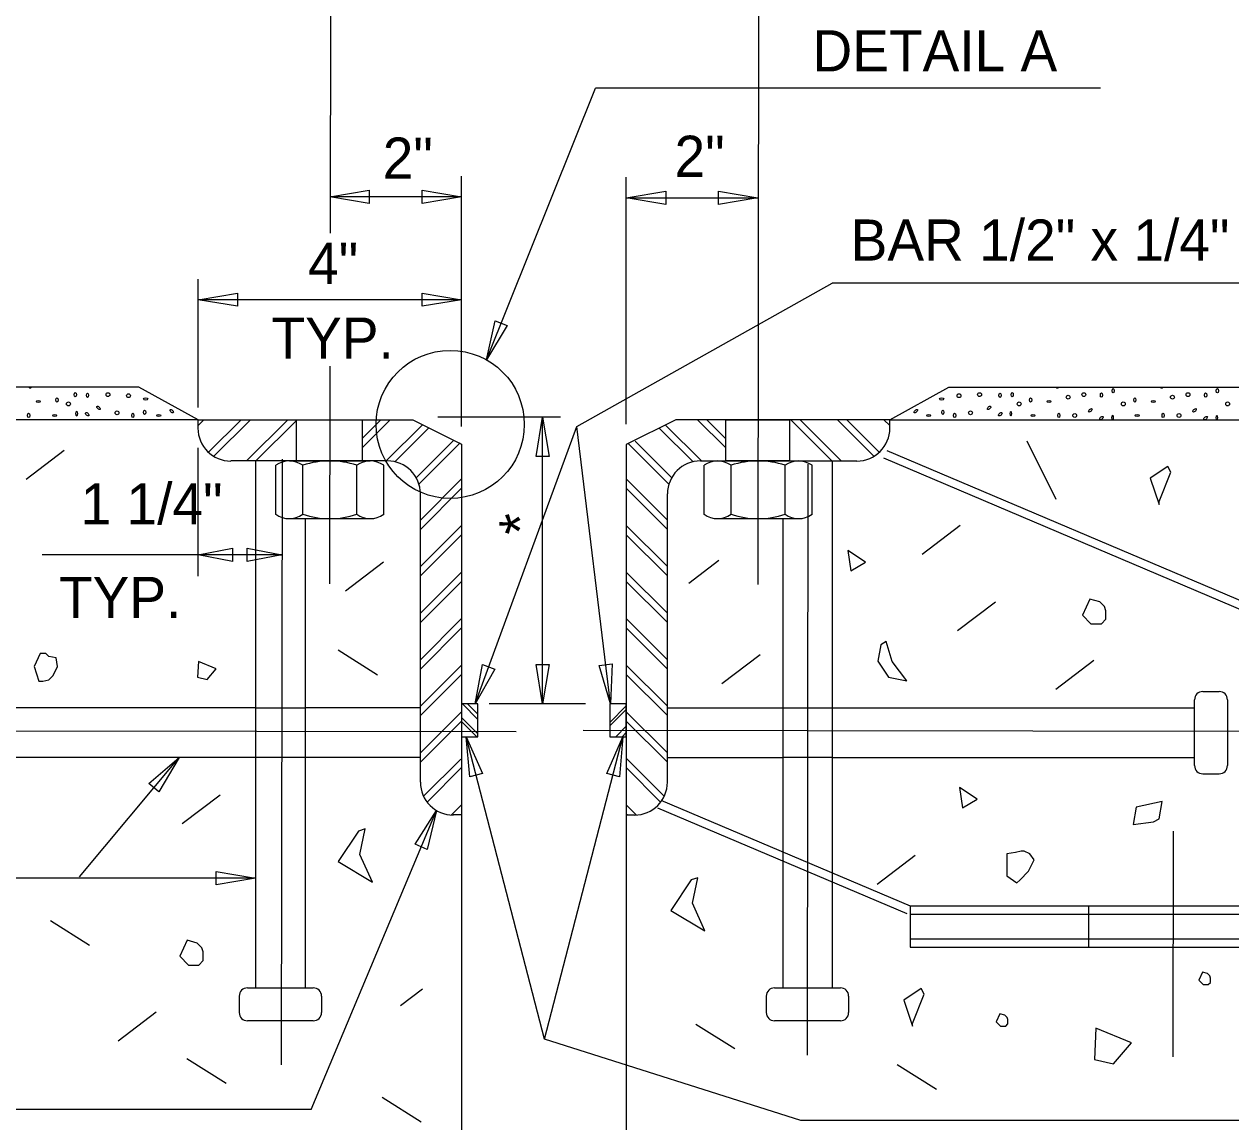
# Model space of a CAD drawing. Extents: x 0 to 11.3, y 0 to 7.8.
# Drawn here: x 2.195 to 3.721, y 1.702 to 3.091 of the extents above; entities that cross this region are included whole.
import ezdxf

# ---------------------------------------------------------------- set-up
doc = ezdxf.new("R2010")
doc.units = 0
for name, color, linetype in [('BRDG_ANNO_General-Notes', 7, 'Continuous'), ('BRDG_BASE_Dtlctrln', 7, 'Continuous'), ('BRDG_BASE_Hidden-Line', 7, 'Continuous'), ('BRDG_BASE_Obj-Line', 7, 'Continuous'), ('BRDG_BASE_Pattern', 7, 'Continuous')]:
    doc.layers.add(name, color=color, linetype=linetype)

msp = doc.modelspace()

# ---------------------------------------------------------------- linework, layer by layer
at = {"layer": 'BRDG_ANNO_General-Notes'}
for p, q in [((2.78, 2.6662), (2.9177, 3.0101)), ((3.5566, 3.0101), (2.9177, 3.0101)), ((2.7484, 2.5817), (2.7484, 2.8984)), ((2.9567, 2.5849), (2.9567, 2.8972)), ((2.5817, 2.8724), (2.6317, 2.8807)), ((2.7484, 2.8724), (2.5817, 2.8724)), ((2.6317, 2.8641), (2.5817, 2.8724)), ((2.6317, 2.8807), (2.6317, 2.8641)), ((2.6984, 2.8641), (2.6984, 2.8807)), ((2.6984, 2.8807), (2.7484, 2.8724)), ((2.7484, 2.8724), (2.6984, 2.8641)), ((2.9567, 2.8711), (3.0067, 2.8795)), ((2.9567, 2.8711), (3.1233, 2.8711)), ((3.0067, 2.8628), (2.9567, 2.8711)), ((3.0067, 2.8795), (3.0067, 2.8628)), ((3.0733, 2.8628), (3.0733, 2.8795)), ((3.0733, 2.8795), (3.1233, 2.8711)), ((3.1233, 2.8711), (3.0733, 2.8628)), ((2.4151, 2.6059), (2.4151, 2.7682)), ((2.8942, 2.5818), (3.2173, 2.7631)), ((3.7564, 2.7631), (3.2173, 2.7631)), ((2.4151, 2.7422), (2.4651, 2.7505)), ((2.4651, 2.7505), (2.4651, 2.7339)), ((2.6984, 2.7339), (2.6984, 2.7505)), ((2.6984, 2.7505), (2.7484, 2.7422)), ((2.7484, 2.7422), (2.4151, 2.7422)), ((2.4651, 2.7339), (2.4151, 2.7422)), ((2.7484, 2.7422), (2.6984, 2.7339)), ((2.78, 2.6662), (2.7908, 2.7157)), ((2.8063, 2.7095), (2.78, 2.6662)), ((2.7908, 2.7157), (2.8063, 2.7095)), ((2.8736, 2.5938), (2.7186, 2.5938)), ((2.7656, 2.2309), (2.8942, 2.5818)), ((2.8426, 2.5437), (2.8509, 2.5938)), ((2.8509, 2.2309), (2.8509, 2.5938)), ((2.8509, 2.5938), (2.8593, 2.5437)), ((2.9366, 2.2309), (2.8942, 2.5818)), ((2.4151, 2.3926), (2.4151, 2.5549)), ((2.8593, 2.5437), (2.8426, 2.5437)), ((2.4151, 2.4195), (2.4588, 2.4279)), ((2.4588, 2.4279), (2.4588, 2.4112)), ((2.4774, 2.4112), (2.4774, 2.4279)), ((2.4774, 2.4279), (2.5212, 2.4195)), ((2.4151, 2.4195), (2.2178, 2.4195)), ((2.5212, 2.4195), (2.4151, 2.4195)), ((2.4588, 2.4112), (2.4151, 2.4195)), ((2.5212, 2.4195), (2.4774, 2.4112)), ((2.5192, 2.4195), (2.5214, 2.4195)), ((2.7656, 2.2309), (2.7749, 2.2807)), ((2.7906, 2.2749), (2.7656, 2.2309)), ((2.7749, 2.2807), (2.7906, 2.2749)), ((2.8426, 2.2809), (2.8593, 2.2809)), ((2.8509, 2.2309), (2.8426, 2.2809)), ((2.8593, 2.2809), (2.8509, 2.2309)), ((2.9223, 2.2795), (2.9389, 2.2815)), ((2.9366, 2.2309), (2.9223, 2.2795)), ((2.9389, 2.2815), (2.9366, 2.2309)), ((2.905, 2.2309), (2.7833, 2.2309)), ((2.8534, 1.8065), (2.7544, 2.1892)), ((2.7589, 2.1387), (2.7544, 2.1892)), ((2.7544, 2.1892), (2.7749, 2.1429)), ((2.8534, 1.8065), (2.9526, 2.1892)), ((2.932, 2.1429), (2.9526, 2.1892)), ((2.9526, 2.1892), (2.9481, 2.1387)), ((2.2654, 2.0119), (2.3911, 2.1632)), ((2.3528, 2.1301), (2.3911, 2.1632)), ((2.3911, 2.1632), (2.3656, 2.1194)), ((2.7749, 2.1429), (2.7589, 2.1387)), ((2.9481, 2.1387), (2.932, 2.1429)), ((2.3656, 2.1194), (2.3528, 2.1301)), ((2.558, 1.7178), (2.7167, 2.0961)), ((2.6896, 2.0533), (2.7167, 2.0961)), ((2.7167, 2.0961), (2.705, 2.0468)), ((2.705, 2.0468), (2.6896, 2.0533)), ((2.438, 2.0021), (2.438, 2.0188)), ((2.438, 2.0188), (2.488, 2.0105)), ((2.488, 2.0105), (0.6091, 2.0105)), ((2.488, 2.0105), (2.438, 2.0021)), ((3.1774, 1.7036), (2.8534, 1.8065)), ((2.558, 1.7178), (0.6091, 1.7178)), ((3.7941, 1.7036), (3.1774, 1.7036))]:
    msp.add_line(p, q, dxfattribs=at)
msp.add_circle((2.7341, 2.5845), 0.0937, dxfattribs=at)
at = {"layer": 'BRDG_BASE_Dtlctrln'}
for p, q in [((2.5838, 4.2478), (2.5821, 2.8266)), ((3.1255, 4.2471), (3.1232, 2.3819)), ((2.5819, 2.6581), (2.5816, 2.3826)), ((2.5214, 2.5404), (2.5204, 1.7741)), ((3.1864, 2.5342), (3.1855, 1.7863)), ((1.9392, 2.1972), (2.8176, 2.1961)), ((2.9021, 2.1974), (3.7739, 2.1963)), ((3.6484, 2.0698), (3.6481, 1.7843))]:
    msp.add_line(p, q, dxfattribs=at)
at = {"layer": 'BRDG_BASE_Hidden-Line'}
for p, q in [((3.2861, 2.5516), (4.6168, 1.9868)), ((3.2821, 2.542), (4.6009, 1.9822)), ((2.488, 2.2257), (2.5505, 2.2257)), ((3.1546, 2.2257), (3.2171, 2.2257)), ((2.5505, 2.1632), (2.488, 2.1632)), ((3.2171, 2.1632), (3.1546, 2.1632)), ((3.0005, 2.109), (3.3156, 1.9752)), ((2.9964, 2.0994), (3.3115, 1.9656)), ((3.3156, 1.9752), (4.6168, 1.9752)), ((3.3156, 1.9752), (3.3156, 1.9231)), ((3.5415, 1.9752), (3.5415, 1.9231)), ((3.3161, 1.9648), (4.6174, 1.9648)), ((3.3156, 1.9231), (4.6168, 1.9231)), ((3.3161, 1.9335), (4.6168, 1.9335))]:
    msp.add_line(p, q, dxfattribs=at)
at = {"layer": 'BRDG_BASE_Obj-Line'}
for p, q in [((2.3403, 2.6315), (1.7493, 2.6315)), ((2.4151, 2.5903), (2.3403, 2.6315)), ((3.2901, 2.5903), (3.3648, 2.6315)), ((3.3648, 2.6315), (3.958, 2.6315)), ((2.4151, 2.5903), (1.7493, 2.5903)), ((2.4151, 2.5903), (2.6867, 2.5903)), ((2.4151, 2.5798), (2.4151, 2.5903)), ((2.6867, 2.5903), (2.7484, 2.5594)), ((3.0194, 2.5903), (2.9567, 2.5589)), ((3.2901, 2.5903), (3.0194, 2.5903)), ((3.2901, 2.5903), (3.958, 2.5903)), ((3.2901, 2.5798), (3.2901, 2.5903)), ((2.7484, 2.5594), (2.7484, 2.0903)), ((2.9567, 2.5589), (2.9567, 2.0903)), ((2.6546, 2.5382), (2.4567, 2.5382)), ((2.488, 2.5382), (2.488, 1.8715)), ((2.5192, 2.5382), (2.5192, 2.5382)), ((2.5309, 2.5382), (2.5818, 2.5382)), ((2.5818, 2.5382), (2.6327, 2.5382)), ((3.0505, 2.5382), (3.2484, 2.5382)), ((3.0726, 2.5382), (3.1234, 2.5382)), ((3.1234, 2.5382), (3.1743, 2.5382)), ((3.2171, 2.5382), (3.2171, 1.8715)), ((2.5134, 2.4707), (2.5134, 2.5328)), ((2.5476, 2.4707), (2.5476, 2.5328)), ((2.6159, 2.4707), (2.6159, 2.5328)), ((2.6502, 2.4707), (2.6502, 2.5328)), ((3.0551, 2.4707), (3.0551, 2.5328)), ((3.0893, 2.4707), (3.0893, 2.5328)), ((3.1576, 2.4707), (3.1576, 2.5328)), ((3.1918, 2.4707), (3.1918, 2.5328)), ((2.6963, 2.1319), (2.6963, 2.4965)), ((3.0088, 2.1319), (3.0088, 2.4965)), ((2.5309, 2.4653), (2.5818, 2.4653)), ((2.5505, 2.4653), (2.5505, 1.8715)), ((2.5818, 2.4653), (2.6327, 2.4653)), ((3.0726, 2.4653), (3.1234, 2.4653)), ((3.1234, 2.4653), (3.1743, 2.4653)), ((3.1546, 2.4653), (3.1546, 1.8715)), ((3.6859, 2.2465), (3.7067, 2.2465)), ((3.6755, 2.2257), (3.6755, 2.2361)), ((3.7171, 2.2361), (3.7171, 2.1528)), ((2.488, 2.2257), (2.0296, 2.2257)), ((2.6963, 2.2257), (2.5505, 2.2257)), ((3.0088, 2.2257), (3.1546, 2.2257)), ((3.2171, 2.2257), (3.6755, 2.2257)), ((3.6755, 2.1528), (3.6755, 2.2257)), ((2.6963, 2.1944), (2.6963, 2.1944)), ((3.0088, 2.1944), (3.0088, 2.1944)), ((2.488, 2.1632), (2.0296, 2.1632)), ((2.6963, 2.1632), (2.5505, 2.1632)), ((3.0088, 2.1632), (3.1546, 2.1632)), ((3.2171, 2.1632), (3.6755, 2.1632)), ((3.6859, 2.1423), (3.7067, 2.1423)), ((2.7484, 2.0903), (2.738, 2.0903)), ((2.7484, 2.0903), (2.7484, 1.3157)), ((2.9567, 2.0903), (2.9567, 1.3157)), ((2.9567, 2.0903), (2.9671, 2.0903)), ((3.3156, 1.9752), (3.3156, 1.9752)), ((2.4776, 1.8715), (2.5505, 1.8715)), ((2.5505, 1.8715), (2.5609, 1.8715)), ((3.1442, 1.8715), (3.2171, 1.8715)), ((3.2171, 1.8715), (3.2276, 1.8715)), ((2.4671, 1.8611), (2.4671, 1.8403)), ((2.5713, 1.8611), (2.5713, 1.8403)), ((3.1338, 1.8611), (3.1338, 1.8403)), ((3.238, 1.8611), (3.238, 1.8403)), ((2.5609, 1.8298), (2.4776, 1.8298)), ((3.2276, 1.8298), (3.1442, 1.8298))]:
    msp.add_line(p, q, dxfattribs=at)
for points in [[(2.5395, 2.5903), (2.6228, 2.5903), (2.6228, 2.5382), (2.5395, 2.5382)], [(3.0827, 2.5903), (3.1633, 2.5903), (3.1633, 2.5382), (3.0827, 2.5382)], [(2.7484, 2.2309), (2.7484, 2.1892), (2.7692, 2.1892), (2.7692, 2.2309)], [(2.9359, 2.2309), (2.9359, 2.1892), (2.9567, 2.1892), (2.9567, 2.2309)]]:
    msp.add_lwpolyline(points, close=True, dxfattribs=at)
msp.add_lwpolyline([(2.9577, 2.0903), (2.9567, 2.0913)], dxfattribs=at)
for centre, radius, start, end in [((2.4567, 2.5798), 0.0417, 180, 270), ((3.2484, 2.5798), 0.0417, 270, 0), ((2.5305, 2.5086), 0.0296, 54.7697, 125.2303), ((2.5818, 2.4278), 0.1104, 71.9685, 108.0316), ((2.633, 2.5086), 0.0296, 54.7697, 125.2303), ((2.6546, 2.4965), 0.0417, 0, 90), ((3.0505, 2.4965), 0.0417, 90, 180), ((3.0722, 2.5086), 0.0296, 54.7697, 125.2303), ((3.1234, 2.4278), 0.1104, 71.9685, 108.0316), ((3.1747, 2.5086), 0.0296, 54.7697, 125.2303), ((2.5305, 2.4949), 0.0296, 234.7697, 305.2303), ((2.5818, 2.5757), 0.1104, 251.9684, 288.0315), ((2.633, 2.4949), 0.0296, 234.7697, 305.2303), ((3.0722, 2.4949), 0.0296, 234.7697, 305.2303), ((3.1234, 2.5757), 0.1104, 251.9684, 288.0315), ((3.1747, 2.4949), 0.0296, 234.7697, 305.2303), ((3.6859, 2.2361), 0.0104, 90, 180), ((3.7067, 2.2361), 0.0104, 0, 90), ((3.6859, 2.1528), 0.0104, 180, 270), ((3.7067, 2.1528), 0.0104, 270, 0), ((2.738, 2.1319), 0.0417, 180, 270), ((2.9671, 2.1319), 0.0417, 270, 0), ((2.4776, 1.8611), 0.0104, 90, 180), ((2.5609, 1.8611), 0.0104, 0, 90), ((3.1442, 1.8611), 0.0104, 90, 180), ((3.2276, 1.8611), 0.0104, 0, 90), ((2.4776, 1.8403), 0.0104, 180, 270), ((2.5609, 1.8403), 0.0104, 270, 0), ((3.1442, 1.8403), 0.0104, 180, 270), ((3.2276, 1.8403), 0.0104, 270, 0)]:
    msp.add_arc(centre, radius, start, end, dxfattribs=at)
at = {"layer": 'BRDG_BASE_Pattern'}
for p, q in [((2.6532, 2.5382), (2.6985, 2.5835)), ((2.6639, 2.5371), (2.7069, 2.5801)), ((3.0412, 2.5371), (2.9984, 2.5799)), ((3.0519, 2.5382), (3.0064, 2.5837)), ((2.2457, 2.5514), (2.1976, 2.5148)), ((2.6909, 2.517), (2.7378, 2.5639)), ((3.0142, 2.517), (2.9678, 2.5634)), ((3.4633, 2.5636), (3.4999, 2.4901)), ((3.3791, 2.4564), (3.3309, 2.4197)), ((3.0738, 2.4121), (3.0359, 2.3833)), ((2.6498, 2.4103), (2.6017, 2.3736)), ((3.4238, 2.3597), (3.3757, 2.3231)), ((2.5924, 2.2991), (2.6419, 2.2678)), ((3.1259, 2.293), (3.0778, 2.2564)), ((3.5481, 2.2857), (3.4999, 2.2491)), ((2.4431, 2.1155), (2.3949, 2.0789)), ((3.322, 2.039), (3.2739, 2.0024)), ((2.2284, 1.9568), (2.278, 1.9256)), ((2.6991, 1.87), (2.6713, 1.8489)), ((2.362, 1.8407), (2.3139, 1.8041)), ((3.0448, 1.8258), (3.0942, 1.7947)), ((2.401, 1.782), (2.4505, 1.7508)), ((3.2995, 1.7747), (3.349, 1.7434)), ((2.6479, 1.7333), (2.6973, 1.7022))]:
    msp.add_line(p, q, dxfattribs=at)
for points in [[(2.4151, 2.5829), (2.4224, 2.5903)], [(2.4285, 2.5492), (2.4695, 2.5903)], [(2.4352, 2.5441), (2.4813, 2.5903)], [(2.4764, 2.5382), (2.5285, 2.5903)], [(2.4882, 2.5382), (2.5395, 2.5895)], [(2.6231, 2.5553), (2.6581, 2.5903)], [(2.6232, 2.5671), (2.6463, 2.5903)], [(3.0822, 2.5551), (3.047, 2.5903)], [(3.0827, 2.5664), (3.0588, 2.5903)], [(3.2169, 2.5382), (3.1648, 2.5903)], [(3.2287, 2.5382), (3.1766, 2.5903)], [(3.2699, 2.5441), (3.2238, 2.5903)], [(3.2766, 2.5492), (3.2356, 2.5903)], [(3.2901, 2.5829), (3.2827, 2.5903)], [(2.6944, 2.5088), (2.7468, 2.5611)], [(3.0107, 2.5088), (2.9596, 2.5598)], [(2.6963, 2.4634), (2.7484, 2.5156)], [(2.6963, 2.4517), (2.7484, 2.5038)], [(3.0088, 2.4634), (2.9567, 2.5156)], [(3.0088, 2.4517), (2.9567, 2.5038)], [(2.6963, 2.4045), (2.7484, 2.4566)], [(2.6963, 2.3928), (2.7484, 2.4448)], [(3.0088, 2.4045), (2.9567, 2.4566)], [(3.0088, 2.3928), (2.9567, 2.4448)], [(2.6963, 2.3456), (2.7484, 2.3977)], [(3.0088, 2.3456), (2.9567, 2.3977)], [(2.6963, 2.3338), (2.7484, 2.3859)], [(3.0088, 2.3338), (2.9567, 2.3859)], [(2.6963, 2.2867), (2.7484, 2.3388)], [(3.0088, 2.2867), (2.9567, 2.3388)], [(2.6963, 2.2749), (2.7484, 2.327)], [(3.0088, 2.2749), (2.9567, 2.327)], [(2.6963, 2.2278), (2.7484, 2.2798)], [(3.0088, 2.2278), (2.9567, 2.2798)], [(2.6963, 2.216), (2.7484, 2.2681)], [(3.0088, 2.216), (2.9567, 2.2681)], [(2.7692, 2.2112), (2.7496, 2.2309)], [(2.7692, 2.2178), (2.7561, 2.2309)], [(2.6963, 2.1688), (2.7484, 2.2209)], [(2.7692, 2.1929), (2.7484, 2.2138)], [(2.9359, 2.2073), (2.9567, 2.2282)], [(2.9359, 2.2029), (2.9567, 2.2237)], [(3.0088, 2.1688), (2.9567, 2.2209)], [(2.6963, 2.157), (2.7484, 2.2092)], [(2.7678, 2.1892), (2.7484, 2.2087)], [(2.9434, 2.1892), (2.9567, 2.2026)], [(3.0088, 2.157), (2.9567, 2.2092)], [(2.9515, 2.1892), (2.9567, 2.1945)], [(2.7004, 2.114), (2.7473, 2.161)], [(3.0047, 2.114), (2.9567, 2.162)], [(2.7049, 2.1067), (2.7484, 2.1502)], [(3.0002, 2.1067), (2.9567, 2.1502)], [(2.7357, 2.0904), (2.7484, 2.1031)], [(2.9694, 2.0904), (2.9567, 2.1031)]]:
    msp.add_lwpolyline(points, dxfattribs=at)
for points in [[(3.6192, 2.5165), (3.6306, 2.4833), (3.6306, 2.4869), (3.6453, 2.5239), (3.6416, 2.5312)], [(3.237, 2.4249), (3.2407, 2.3991), (3.2592, 2.4102)], [(3.543, 2.3634), (3.5337, 2.3432), (3.5445, 2.332), (3.5578, 2.332), (3.5632, 2.3379), (3.5632, 2.3486), (3.5614, 2.354), (3.5556, 2.3599)], [(3.2789, 2.3057), (3.2748, 2.285), (3.2886, 2.2647), (3.3116, 2.2602), (3.2932, 2.2845), (3.2854, 2.3098)], [(2.2079, 2.278), (2.2137, 2.2596), (2.219, 2.2596), (2.2265, 2.2614), (2.2319, 2.2668), (2.2373, 2.278), (2.2358, 2.289), (2.2265, 2.2909), (2.2226, 2.2947), (2.2153, 2.2947)], [(2.4155, 2.2844), (2.4146, 2.2646), (2.4265, 2.2618), (2.438, 2.2752)], [(3.3784, 2.1252), (3.3821, 2.0993), (3.4006, 2.1104)], [(3.6015, 2.1001), (3.5978, 2.0781), (3.6236, 2.0818), (3.6309, 2.0854), (3.6346, 2.1075)], [(2.6181, 2.0699), (2.5924, 2.0314), (2.6357, 2.0054), (2.6199, 2.0405), (2.6266, 2.0726)], [(3.438, 2.0411), (3.438, 2.0132), (3.4506, 2.0043), (3.4545, 2.0079), (3.4653, 2.019), (3.4727, 2.0337), (3.4673, 2.0411), (3.4599, 2.0447), (3.4564, 2.0447), (3.4491, 2.0427)], [(3.0387, 2.0081), (3.013, 1.9696), (3.0562, 1.9436), (3.0405, 1.9787), (3.0471, 2.0108)], [(2.4015, 1.9318), (2.3922, 1.9116), (2.403, 1.9004), (2.4162, 1.9004), (2.4217, 1.9062), (2.4217, 1.917), (2.4198, 1.9223), (2.4141, 1.9283)], [(3.6855, 1.8914), (3.6809, 1.8812), (3.6863, 1.8756), (3.6929, 1.8756), (3.6956, 1.8785), (3.6956, 1.884), (3.6947, 1.8866), (3.6919, 1.8896)], [(3.3076, 1.8561), (3.3189, 1.8229), (3.3189, 1.8264), (3.3337, 1.8634), (3.3299, 1.8708)], [(3.4293, 1.8388), (3.4246, 1.8286), (3.4301, 1.823), (3.4367, 1.823), (3.4394, 1.826), (3.4394, 1.8314), (3.4385, 1.8341), (3.4356, 1.837)], [(3.5508, 1.8204), (3.549, 1.7808), (3.5729, 1.7753), (3.5959, 1.802)]]:
    msp.add_lwpolyline(points, close=True, dxfattribs=at)
for centre in [(2.2512, 2.6104), (2.3012, 2.6222), (2.3272, 2.6208), (3.3776, 2.6208), (3.4036, 2.6222), (3.4536, 2.6104), (3.5157, 2.619), (3.5354, 2.6222), (3.5854, 2.6104), (3.6475, 2.619), (3.6672, 2.6222), (3.7173, 2.6104), (2.3127, 2.5992), (3.3921, 2.5992), (3.5239, 2.5958), (3.6558, 2.5958)]:
    msp.add_circle(centre, 0.00244, dxfattribs=at)
for centre, start, end in [((2.2028, 2.6331), 222.2524, 317.7477), ((3.502, 2.6331), 222.2523, 317.7476), ((3.6338, 2.6331), 222.2523, 317.7476)]:
    msp.add_arc(centre, 0.00244, start, end, dxfattribs=at)
for centre, major_axis in [((3.5726, 2.627), (0, -0.00275)), ((3.7044, 2.627), (0, -0.00275)), ((2.2132, 2.6135), (-0.00275, 0)), ((2.2367, 2.6154), (0, -0.00275)), ((2.2599, 2.622), (0, -0.00275)), ((2.2753, 2.6213), (0, -0.00275)), ((2.349, 2.6166), (-0.00275, 0)), ((3.3558, 2.6166), (0.00275, 0)), ((3.4295, 2.6213), (0, -0.00275)), ((3.4449, 2.622), (0, -0.00275)), ((3.4681, 2.6154), (0, -0.00275)), ((3.4915, 2.6135), (0.00275, 0)), ((3.5577, 2.6215), (0, -0.00275)), ((3.5999, 2.6154), (0, -0.00275)), ((3.6234, 2.6135), (0.00275, 0)), ((3.6895, 2.6215), (0, -0.00275)), ((2.2009, 2.5958), (0, -0.00275)), ((2.2337, 2.5957), (-0.00275, 0)), ((2.275, 2.5973), (0.00195, -0.00195)), ((2.2892, 2.6054), (0.00195, -0.00195)), ((2.3327, 2.5958), (0, -0.00275)), ((2.3476, 2.5999), (0, -0.00275)), ((2.3655, 2.5957), (-0.00275, 0)), ((2.3818, 2.6012), (0.00195, -0.00195)), ((3.323, 2.6012), (-0.00195, -0.00195)), ((3.3393, 2.5957), (0.00275, 0)), ((3.3571, 2.5999), (0, -0.00275)), ((3.372, 2.5958), (0, -0.00275)), ((3.4156, 2.6054), (-0.00195, -0.00195)), ((3.4298, 2.5973), (-0.00195, -0.00195)), ((3.4711, 2.5957), (0.00275, 0)), ((3.5039, 2.5958), (0, -0.00275)), ((3.5437, 2.6023), (-0.00195, -0.00195)), ((3.5577, 2.5925), (-0.00195, -0.00195)), ((3.6029, 2.5957), (0.00275, 0)), ((3.6357, 2.5958), (0, -0.00275)), ((3.6755, 2.6023), (-0.00195, -0.00195)), ((3.6895, 2.5925), (-0.00195, -0.00195))]:
    msp.add_ellipse(centre, major_axis=major_axis, ratio=0.5, dxfattribs=at)
for centre in [(2.2617, 2.5981), (3.4431, 2.5981), (3.5718, 2.593), (3.7036, 2.593)]:
    msp.add_ellipse(centre, major_axis=(0, -0.00275), ratio=0.5, start_param=0.00615, end_param=6.277035, dxfattribs=at)

# ---------------------------------------------------------------- texts
at = {"layer": 'BRDG_ANNO_General-Notes'}
for s, height, p in [('DETAIL A', 0.05208, (3.1922, 3.0312)), ('2"', 0.05208, (2.6487, 2.8954)), ('2"', 0.05208, (3.0178, 2.8977)), ('BAR 1/2" x 1/4"', 0.052083, (3.2405, 2.7917)), ('4"', 0.05208, (2.5543, 2.7622)), ('TYP.', 0.05208, (2.508, 2.6676)), ('1 1/4"', 0.05208, (2.2666, 2.4579)), ('TYP.', 0.05208, (2.2392, 2.3395))]:
    msp.add_text(s, height=height, dxfattribs=at).set_placement(p)
msp.add_text('*', height=0.0521, rotation=90, dxfattribs=at).set_placement((2.8484, 2.445))

doc.saveas('drawing.dxf')
